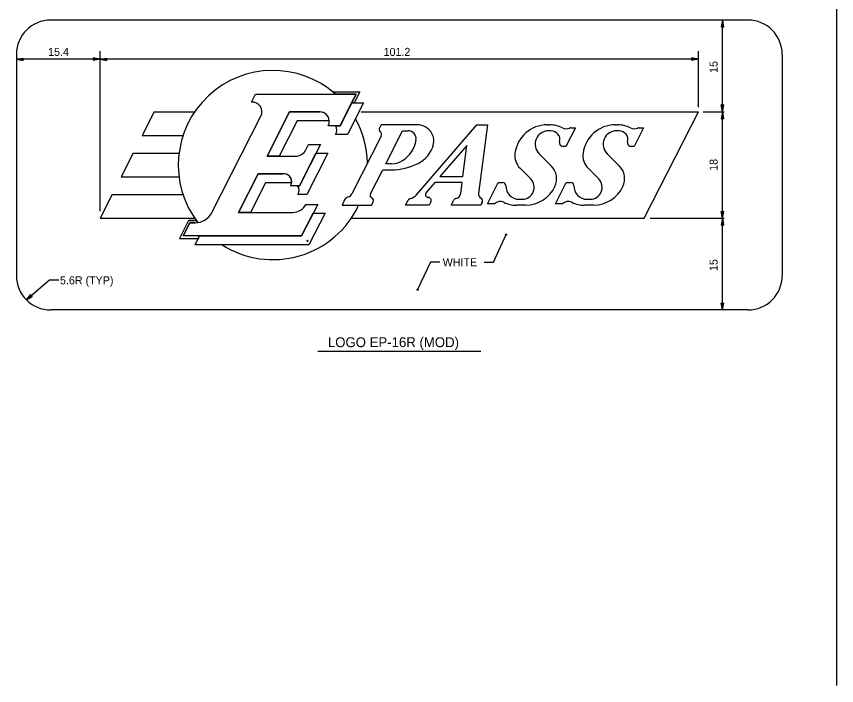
# Model space of a CAD drawing. Extents: x 10268197 to 10268739, y 2141503 to 2142677.
# Drawn here: x 10268592.6 to 10268664.3, y 2142335.6 to 2142394.2 of the extents above; entities that cross this region are included whole.
import ezdxf

# ---------------------------------------------------------------- set-up
doc = ezdxf.new("R2010")
doc.units = 0
for name, color, linetype in [('1', 7, 'Continuous'), ('21', 7, 'Continuous'), ('Default', 7, 'Continuous'), ('NonPlottingEle_dp', 7, 'Continuous')]:
    doc.layers.add(name, color=color, linetype=linetype)

msp = doc.modelspace()

# ---------------------------------------------------------------- linework, layer by layer
at = {"layer": '1'}
for p, q in [((10268654.33, 2142393.836), (10268654.214, 2142393.234)), ((10268654.33, 2142393.836), (10268654.27, 2142393.257)), ((10268654.33, 2142385.809), (10268654.33, 2142393.836)), ((10268654.33, 2142393.836), (10268654.426, 2142393.23)), ((10268654.33, 2142393.836), (10268654.371, 2142393.256)), ((10268654.214, 2142393.234), (10268654.321, 2142393.278)), ((10268654.321, 2142393.278), (10268654.426, 2142393.23)), ((10268599.881, 2142377.104), (10268599.881, 2142391.116)), ((10268652.242, 2142386.223), (10268652.242, 2142391.116)), ((10268599.324, 2142390.421), (10268599.276, 2142390.315)), ((10268599.881, 2142390.412), (10268599.276, 2142390.315)), ((10268599.881, 2142390.412), (10268599.279, 2142390.528)), ((10268599.279, 2142390.528), (10268599.324, 2142390.421)), ((10268599.881, 2142390.412), (10268599.302, 2142390.371)), ((10268599.881, 2142390.412), (10268599.303, 2142390.472)), ((10268651.685, 2142390.421), (10268651.636, 2142390.315)), ((10268652.242, 2142390.412), (10268651.636, 2142390.315)), ((10268652.242, 2142390.412), (10268651.64, 2142390.528)), ((10268651.64, 2142390.528), (10268651.685, 2142390.421)), ((10268652.242, 2142390.412), (10268651.662, 2142390.371)), ((10268652.242, 2142390.412), (10268651.664, 2142390.472)), ((10268620.875, 2142384.593), (10268621.891, 2142386.585)), ((10268622.937, 2142386.585), (10268621.526, 2142383.818)), ((10268621.891, 2142386.585), (10268622.937, 2142386.585)), ((10268614.492, 2142381.928), (10268616.47, 2142385.809)), ((10268616.47, 2142385.809), (10268619.108, 2142385.809)), ((10268652.656, 2142385.809), (10268654.487, 2142385.809)), ((10268654.33, 2142385.809), (10268654.214, 2142385.208)), ((10268654.33, 2142385.809), (10268654.235, 2142386.415)), ((10268654.34, 2142386.367), (10268654.235, 2142386.415)), ((10268654.33, 2142385.809), (10268654.27, 2142385.231)), ((10268654.33, 2142385.809), (10268654.29, 2142386.389)), ((10268654.33, 2142385.809), (10268654.447, 2142386.411)), ((10268654.33, 2142385.809), (10268654.391, 2142386.388)), ((10268654.33, 2142376.493), (10268654.33, 2142385.809)), ((10268654.33, 2142385.809), (10268654.426, 2142385.204)), ((10268654.33, 2142385.809), (10268654.371, 2142385.23)), ((10268654.447, 2142386.411), (10268654.34, 2142386.367)), ((10268617.12, 2142385.033), (10268615.538, 2142381.928)), ((10268619.935, 2142385.033), (10268617.12, 2142385.033)), ((10268654.214, 2142385.208), (10268654.321, 2142385.252)), ((10268654.321, 2142385.252), (10268654.426, 2142385.204)), ((10268620.49, 2142384.593), (10268620.875, 2142384.593)), ((10268621.526, 2142383.818), (10268620.491, 2142383.818)), ((10268617.319, 2142379.34), (10268618.77, 2142382.187)), ((10268619.815, 2142382.187), (10268617.97, 2142378.563)), ((10268618.77, 2142382.187), (10268619.815, 2142382.187)), ((10268615.538, 2142381.928), (10268614.492, 2142381.928)), ((10268611.988, 2142377.011), (10268613.702, 2142380.375)), ((10268613.702, 2142380.375), (10268615.875, 2142380.368)), ((10268614.351, 2142379.597), (10268613.033, 2142377.011)), ((10268616.636, 2142379.589), (10268614.351, 2142379.597)), ((10268617.157, 2142379.34), (10268617.319, 2142379.34)), ((10268617.97, 2142378.563), (10268617.193, 2142378.563)), ((10268613.033, 2142377.011), (10268611.988, 2142377.011)), ((10268617.511, 2142374.941), (10268618.525, 2142376.931)), ((10268619.571, 2142376.931), (10268618.161, 2142374.164)), ((10268618.525, 2142376.931), (10268619.571, 2142376.931)), ((10268648.013, 2142376.493), (10268654.487, 2142376.493)), ((10268654.33, 2142376.493), (10268654.214, 2142375.891)), ((10268654.33, 2142376.493), (10268654.235, 2142377.099)), ((10268654.34, 2142377.051), (10268654.235, 2142377.099)), ((10268654.33, 2142376.493), (10268654.27, 2142375.914)), ((10268654.33, 2142376.493), (10268654.29, 2142377.073)), ((10268654.33, 2142376.493), (10268654.447, 2142377.095)), ((10268654.33, 2142376.493), (10268654.391, 2142377.072)), ((10268654.33, 2142368.467), (10268654.33, 2142376.493)), ((10268654.33, 2142376.493), (10268654.426, 2142375.888)), ((10268654.33, 2142376.493), (10268654.371, 2142375.914)), ((10268654.447, 2142377.095), (10268654.34, 2142377.051)), ((10268654.214, 2142375.891), (10268654.321, 2142375.936)), ((10268654.321, 2142375.936), (10268654.426, 2142375.888)), ((10268634.302, 2142372.655), (10268635.417, 2142375.063)), ((10268608.195, 2142374.164), (10268608.591, 2142374.941)), ((10268608.591, 2142374.941), (10268617.511, 2142374.941)), ((10268618.161, 2142374.164), (10268608.195, 2142374.164)), ((10268628.779, 2142372.655), (10268627.664, 2142370.248)), ((10268629.601, 2142372.655), (10268628.779, 2142372.655)), ((10268633.48, 2142372.655), (10268634.302, 2142372.655)), ((10268595.452, 2142371.076), (10268593.44, 2142369.345)), ((10268596.274, 2142371.076), (10268595.452, 2142371.076)), ((10268654.33, 2142368.467), (10268654.235, 2142369.072)), ((10268654.34, 2142369.024), (10268654.235, 2142369.072)), ((10268654.33, 2142368.467), (10268654.29, 2142369.047)), ((10268654.33, 2142368.467), (10268654.447, 2142369.069)), ((10268654.33, 2142368.467), (10268654.391, 2142369.046)), ((10268654.447, 2142369.069), (10268654.34, 2142369.024))]:
    msp.add_line(p, q, dxfattribs=at)
msp.add_lwpolyline([(10268620.25, 2142387.562), (10268622.621, 2142387.562), (10268622.124, 2142386.585), (10268621.891, 2142386.585), (10268622.287, 2142387.362), (10268620.485, 2142387.362)], close=True, dxfattribs=at)
for centre in [(10268635.417, 2142375.063), (10268618.028, 2142374.519), (10268627.664, 2142370.248)]:
    msp.add_circle(centre, 0.0518, dxfattribs=at)
for centre, radius, start, end in [((10268619.108, 2142384.981), 0.828, 3.58332, 90), ((10268619.758, 2142384.205), 0.828, 332.20885, 27.91266), ((10268615.973, 2142379.702), 0.673, 350.35016, 98.33436), ((10268616.627, 2142378.926), 0.673, 327.42103, 37.97987)]:
    msp.add_arc(centre, radius, start, end, dxfattribs=at)
at = {"layer": '21'}
for p, q in [((10268592.562, 2142390.412), (10268593.167, 2142390.508)), ((10268592.562, 2142390.412), (10268593.142, 2142390.452)), ((10268592.562, 2142390.412), (10268593.163, 2142390.295)), ((10268592.562, 2142390.412), (10268593.14, 2142390.351)), ((10268593.119, 2142390.402), (10268593.167, 2142390.508)), ((10268593.163, 2142390.295), (10268593.119, 2142390.402)), ((10268599.881, 2142390.412), (10268600.486, 2142390.508)), ((10268599.881, 2142390.412), (10268600.461, 2142390.452)), ((10268599.881, 2142390.412), (10268600.483, 2142390.295)), ((10268599.881, 2142390.412), (10268600.46, 2142390.351)), ((10268600.439, 2142390.402), (10268600.486, 2142390.508)), ((10268600.483, 2142390.295), (10268600.439, 2142390.402)), ((10268593.44, 2142369.345), (10268593.828, 2142369.82)), ((10268593.44, 2142369.345), (10268593.846, 2142369.761)), ((10268593.44, 2142369.345), (10268593.912, 2142369.685)), ((10268593.44, 2142369.345), (10268593.967, 2142369.658)), ((10268593.863, 2142369.709), (10268593.828, 2142369.82)), ((10268593.967, 2142369.658), (10268593.863, 2142369.709)), ((10268618.924, 2142364.858), (10268633.199, 2142364.858))]:
    msp.add_line(p, q, dxfattribs=at)
at = {"layer": 'Default'}
for p, q in [((10268656.562, 2142393.836), (10268595.562, 2142393.836)), ((10268592.562, 2142390.836), (10268592.562, 2142371.467)), ((10268659.562, 2142390.836), (10268659.562, 2142371.467)), ((10268599.881, 2142390.412), (10268592.562, 2142390.412)), ((10268652.242, 2142390.412), (10268599.881, 2142390.412)), ((10268613.135, 2142386.668), (10268613.488, 2142387.362)), ((10268613.488, 2142387.362), (10268622.287, 2142387.362)), ((10268620.25, 2142387.562), (10268622.621, 2142387.562)), ((10268622.287, 2142387.362), (10268620.877, 2142384.595)), ((10268622.621, 2142387.562), (10268622.124, 2142386.585)), ((10268620.875, 2142384.593), (10268621.891, 2142386.585)), ((10268622.937, 2142386.585), (10268621.526, 2142383.818)), ((10268621.891, 2142386.585), (10268622.937, 2142386.585)), ((10268604.628, 2142385.809), (10268603.573, 2142383.739)), ((10268604.628, 2142385.809), (10268608.161, 2142385.809)), ((10268616.47, 2142385.809), (10268614.492, 2142381.928)), ((10268614.492, 2142381.928), (10268616.47, 2142385.809)), ((10268619.108, 2142385.809), (10268616.47, 2142385.809)), ((10268616.47, 2142385.809), (10268619.108, 2142385.809)), ((10268622.718, 2142385.809), (10268652.242, 2142385.809)), ((10268647.496, 2142376.493), (10268652.242, 2142385.809)), ((10268609.657, 2142376.998), (10268613.952, 2142385.428)), ((10268617.12, 2142385.033), (10268615.538, 2142381.928)), ((10268619.935, 2142385.033), (10268617.12, 2142385.033)), ((10268620.877, 2142384.595), (10268619.841, 2142384.595)), ((10268620.49, 2142384.593), (10268620.875, 2142384.593)), ((10268624.464, 2142384.671), (10268624.323, 2142384.392)), ((10268627.634, 2142384.671), (10268624.464, 2142384.671)), ((10268627.554, 2142378.546), (10268632.839, 2142384.671)), ((10268632.839, 2142384.671), (10268633.771, 2142384.671)), ((10268633.771, 2142384.671), (10268632.996, 2142378.671)), ((10268639.006, 2142384.671), (10268639.202, 2142384.671)), ((10268641.468, 2142384.41), (10268640.646, 2142382.784)), ((10268641.08, 2142384.41), (10268641.468, 2142384.41)), ((10268644.958, 2142384.671), (10268645.154, 2142384.671)), ((10268647.42, 2142384.41), (10268646.597, 2142382.784)), ((10268647.032, 2142384.41), (10268647.42, 2142384.41)), ((10268603.573, 2142383.739), (10268607.142, 2142383.739)), ((10268621.526, 2142383.818), (10268620.491, 2142383.818)), ((10268624.473, 2142383.685), (10268621.911, 2142378.618)), ((10268624.871, 2142381.255), (10268626.335, 2142384.149)), ((10268626.335, 2142384.149), (10268626.834, 2142384.149)), ((10268639.334, 2142384.149), (10268639.112, 2142384.149)), ((10268645.285, 2142384.149), (10268645.063, 2142384.149)), ((10268619.165, 2142382.963), (10268617.319, 2142379.34)), ((10268617.89, 2142382.493), (10268618.13, 2142382.963)), ((10268618.13, 2142382.963), (10268619.165, 2142382.963)), ((10268631.973, 2142382.872), (10268629.61, 2142380.134)), ((10268631.619, 2142380.134), (10268631.973, 2142382.872)), ((10268602.782, 2142382.187), (10268601.727, 2142380.116)), ((10268602.782, 2142382.187), (10268606.792, 2142382.187)), ((10268617.319, 2142379.34), (10268618.77, 2142382.187)), ((10268619.815, 2142382.187), (10268617.97, 2142378.563)), ((10268618.77, 2142382.187), (10268619.815, 2142382.187)), ((10268638.288, 2142382.146), (10268639.373, 2142381.054)), ((10268640.646, 2142382.784), (10268640.387, 2142382.784)), ((10268644.24, 2142382.146), (10268645.325, 2142381.054)), ((10268646.597, 2142382.784), (10268646.338, 2142382.784)), ((10268614.492, 2142381.928), (10268616.969, 2142381.928)), ((10268615.538, 2142381.928), (10268614.492, 2142381.928)), ((10268623.537, 2142378.619), (10268624.607, 2142380.734)), ((10268624.607, 2142380.734), (10268625.383, 2142380.734)), ((10268625.383, 2142381.255), (10268624.871, 2142381.255)), ((10268637.557, 2142379.934), (10268636.626, 2142380.871)), ((10268643.508, 2142379.934), (10268642.577, 2142380.871)), ((10268601.727, 2142380.116), (10268606.792, 2142380.116)), ((10268613.702, 2142380.375), (10268611.988, 2142377.011)), ((10268611.988, 2142377.011), (10268613.702, 2142380.375)), ((10268615.973, 2142380.375), (10268613.702, 2142380.375)), ((10268613.702, 2142380.375), (10268615.875, 2142380.368)), ((10268629.61, 2142380.134), (10268631.619, 2142380.134)), ((10268614.351, 2142379.597), (10268613.033, 2142377.011)), ((10268616.636, 2142379.589), (10268614.351, 2142379.597)), ((10268617.319, 2142379.34), (10268616.54, 2142379.34)), ((10268617.157, 2142379.34), (10268617.319, 2142379.34)), ((10268629.162, 2142379.613), (10268628.411, 2142378.743)), ((10268631.567, 2142379.613), (10268629.162, 2142379.613)), ((10268631.444, 2142378.671), (10268631.567, 2142379.613)), ((10268633.767, 2142377.762), (10268634.707, 2142379.621)), ((10268634.707, 2142379.621), (10268635.122, 2142379.621)), ((10268639.719, 2142377.762), (10268640.659, 2142379.621)), ((10268640.659, 2142379.621), (10268641.075, 2142379.621)), ((10268600.936, 2142378.563), (10268599.881, 2142376.493)), ((10268600.936, 2142378.563), (10268607.142, 2142378.563)), ((10268617.97, 2142378.563), (10268617.193, 2142378.563)), ((10268621.281, 2142378.092), (10268621.049, 2142377.632)), ((10268623.637, 2142377.632), (10268623.778, 2142377.91)), ((10268626.602, 2142377.632), (10268626.827, 2142378.077)), ((10268628.825, 2142377.933), (10268628.672, 2142377.632)), ((10268630.596, 2142377.632), (10268630.824, 2142378.084)), ((10268633.32, 2142377.901), (10268633.184, 2142377.632)), ((10268636.546, 2142378.153), (10268636.825, 2142378.153)), ((10268642.498, 2142378.153), (10268642.777, 2142378.153)), ((10268618.921, 2142377.707), (10268617.511, 2142374.941)), ((10268617.885, 2142377.707), (10268618.921, 2142377.707)), ((10268621.049, 2142377.632), (10268623.637, 2142377.632)), ((10268628.672, 2142377.632), (10268626.602, 2142377.632)), ((10268633.184, 2142377.632), (10268630.596, 2142377.632)), ((10268634.396, 2142377.762), (10268633.767, 2142377.762)), ((10268637.103, 2142377.632), (10268636.325, 2142377.632)), ((10268640.348, 2142377.762), (10268639.719, 2142377.762)), ((10268643.055, 2142377.632), (10268642.276, 2142377.632)), ((10268599.881, 2142376.493), (10268608.161, 2142376.493)), ((10268611.988, 2142377.011), (10268616.737, 2142377.011)), ((10268613.033, 2142377.011), (10268611.988, 2142377.011)), ((10268617.511, 2142374.941), (10268618.525, 2142376.931)), ((10268619.571, 2142376.931), (10268618.161, 2142374.164)), ((10268618.525, 2142376.931), (10268619.571, 2142376.931)), ((10268621.854, 2142376.493), (10268647.496, 2142376.493)), ((10268607.62, 2142376.301), (10268606.822, 2142374.733)), ((10268607.16, 2142374.941), (10268607.747, 2142376.094)), ((10268607.747, 2142376.094), (10268607.161, 2142374.941)), ((10268607.62, 2142376.301), (10268608.296, 2142376.301)), ((10268607.747, 2142376.094), (10268608.182, 2142376.094)), ((10268608.182, 2142376.094), (10268607.747, 2142376.094)), ((10268606.822, 2142374.733), (10268608.485, 2142374.733)), ((10268617.511, 2142374.941), (10268607.16, 2142374.941)), ((10268608.195, 2142374.164), (10268608.591, 2142374.941)), ((10268608.591, 2142374.941), (10268617.511, 2142374.941)), ((10268618.161, 2142374.164), (10268608.195, 2142374.164)), ((10268656.562, 2142368.467), (10268595.562, 2142368.467))]:
    msp.add_line(p, q, dxfattribs=at)
msp.add_lwpolyline([(10268608.296, 2142376.301), (10268607.62, 2142376.301), (10268606.822, 2142374.733), (10268608.485, 2142374.733), (10268608.591, 2142374.941), (10268607.16, 2142374.941), (10268607.747, 2142376.094), (10268608.182, 2142376.094), (10268608.436, 2142376.114)], close=True, dxfattribs=at)
for centre, radius, start, end in [((10268595.562, 2142390.836), 3, 90, 180), ((10268656.562, 2142390.836), 3, 0, 90), ((10268615.008, 2142381.152), 8.281, 48.59038, 217.47245), ((10268613.192, 2142385.816), 0.854, 332.99985, 93.80449), ((10268619.108, 2142384.981), 0.828, 332.20885, 90), ((10268619.108, 2142384.981), 0.828, 3.58332, 90), ((10268615.008, 2142381.152), 8.281, 1.29669, 29.27782), ((10268619.758, 2142384.205), 0.828, 332.20885, 27.91266), ((10268616.969, 2142382.963), 1.035, 270, 332.98829), ((10268615.973, 2142379.702), 0.673, 350.35016, 98.33436), ((10268615.973, 2142379.702), 0.673, 327.42103, 90), ((10268616.627, 2142378.926), 0.673, 327.42103, 37.97987), ((10268615.008, 2142381.152), 8.281, 237.53826, 334.84934), ((10268616.737, 2142378.305), 1.294, 270, 332.5096), ((10268608.182, 2142377.75), 1.656, 270, 332.99913), ((10268595.562, 2142371.467), 3, 180, 270), ((10268656.562, 2142371.467), 3, 270, 0)]:
    msp.add_arc(centre, radius, start, end, dxfattribs=at)
for centre, major_axis, start_param, end_param in [((10268624.554, 2142384.274), (0, -0.261), 4.240773, 5.605302), ((10268627.634, 2142383.185), (0, 1.486), 5.226065, 6.283185), ((10268639.006, 2142381.803), (0, 2.868), 0, 1.436562), ((10268639.202, 2142382.064), (0, 2.607), 5.830963, 6.283185), ((10268640.672, 2142385.112), (0, 0.782), 2.68937, 3.526171), ((10268641.08, 2142384.097), (0, 0.313), 0, 0.384579), ((10268644.957, 2142381.803), (0, 2.868), 0, 1.436562), ((10268645.154, 2142382.064), (0, 2.607), 5.830963, 6.283185), ((10268646.624, 2142385.112), (0, 0.782), 2.68937, 3.526171), ((10268647.031, 2142384.097), (0, 0.313), 0, 0.384579), ((10268624.197, 2142383.828), (0, -0.313), 1.099604, 2.46371), ((10268626.833, 2142383.446), (0, -0.704), 1.415043, 3.141593), ((10268627.792, 2142383.274), (0, 1.303), 4.445482, 5.226065), ((10268639.111, 2142382.976), (0, -1.173), 3.141593, 5.497787), ((10268639.334, 2142383.367), (0, -0.782), 1.321066, 3.141593), ((10268645.063, 2142382.976), (0, -1.173), 3.141593, 5.497787), ((10268645.285, 2142383.367), (0, -0.782), 1.321066, 3.141593), ((10268624.967, 2142383.741), (0, -2.607), 0.565847, 1.415043), ((10268626.544, 2142383.618), (0, -2.607), 0.465011, 1.30389), ((10268640.387, 2142383.097), (0, -0.313), 4.462658, 6.283185), ((10268646.338, 2142383.097), (0, -0.313), 4.462658, 6.283185), ((10268637.723, 2142381.978), (0, 1.564), 1.436562, 2.356194), ((10268643.675, 2142381.978), (0, 1.564), 1.436562, 2.356194), ((10268625.383, 2142383.081), (0, -1.825), 0, 0.565847), ((10268625.383, 2142385.948), (0, -5.214), 0, 0.465011), ((10268638.275, 2142379.948), (0, -1.564), 1.133591, 2.356194), ((10268644.227, 2142379.948), (0, -1.564), 1.133591, 2.356194), ((10268635.123, 2142379.36), (0, 0.261), 4.689114, 6.283185), ((10268636.546, 2142379.327), (0, 1.173), 1.547521, 3.141593), ((10268636.825, 2142379.196), (0, -1.043), 0, 2.356194), ((10268637.103, 2142380.5), (0, -2.868), 0, 1.133591), ((10268641.075, 2142379.36), (0, 0.261), 4.689114, 6.283185), ((10268642.497, 2142379.327), (0, 1.173), 1.547521, 3.141593), ((10268642.776, 2142379.196), (0, -1.043), 0, 2.356194), ((10268643.055, 2142380.5), (0, -2.868), 0, 1.133591), ((10268621.45, 2142378.855), (0, -0.521), 0.286787, 1.099486), ((10268623.767, 2142378.501), (0, 0.261), 1.099355, 2.701477), ((10268628.606, 2142378.573), (0, 0.261), 0.854904, 3.118676), ((10268630.931, 2142378.738), (0, -0.521), 0.161263, 1.440999), ((10268633.407, 2142378.617), (0, 0.417), 1.441439, 2.650585), ((10268621.743, 2142377.855), (0, -0.521), 3.428379, 4.240701), ((10268623.547, 2142378.029), (0, 0.261), 4.241567, 5.84307), ((10268627.058, 2142377.96), (0, -0.261), 3.363532, 4.241567), ((10268626.773, 2142379.231), (0, -1.043), 0.22194, 0.855152), ((10268628.595, 2142378.052), (0, 0.261), 4.240773, 6.260268), ((10268631.055, 2142377.966), (0, -0.261), 3.302856, 4.241567), ((10268633.089, 2142378.019), (0, 0.261), 4.240773, 5.792177), ((10268634.892, 2142377.23), (0, -0.73), 2.69443, 3.895387), ((10268636.324, 2142380.239), (0, -2.607), 5.836023, 6.283185), ((10268640.844, 2142377.23), (0, -0.73), 2.69443, 3.895387), ((10268642.276, 2142380.239), (0, -2.607), 5.836023, 6.283185)]:
    msp.add_ellipse(centre, major_axis=major_axis, ratio=0.992614, start_param=start_param, end_param=end_param, dxfattribs=at)
at = {"layer": 'NonPlottingEle_dp'}
msp.add_line((10268664.322, 2142431.588), (10268664.322, 2142335.588), dxfattribs=at)

# ---------------------------------------------------------------- texts
at = {"layer": '1'}
for s, height, p in [('15.4', 0.7, (10268595.334, 2142390.706)), ('101.2', 0.7, (10268624.687, 2142390.706)), ('WHITE', 0.7, (10268629.857, 2142372.293)), ('5.6R (TYP)', 0.7, (10268596.375, 2142370.713)), ('LOGO EP-16R (MOD)', 0.8624, (10268619.815, 2142365.211))]:
    msp.add_text(s, height=height, dxfattribs=at).set_placement(p)
for s, p in [('15', (10268653.909, 2142389.217)), ('18', (10268653.909, 2142380.647)), ('15', (10268653.909, 2142371.875))]:
    msp.add_text(s, height=0.7, rotation=90, dxfattribs=at).set_placement(p)

doc.saveas('drawing.dxf')
